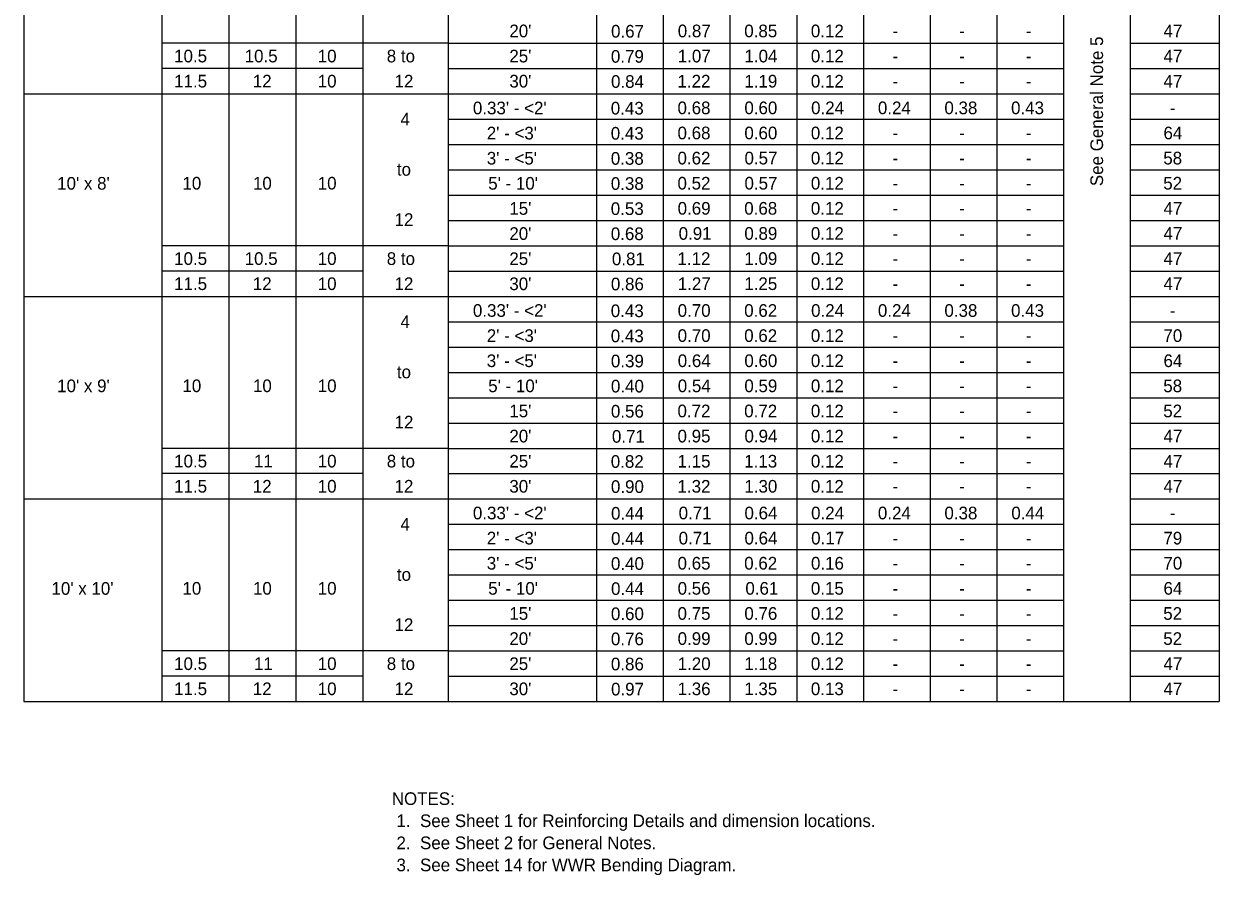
# Model space of a CAD drawing. Extents: x 10346.98 to 10349.19, y 76399.48 to 76400.59.
# Drawn here: x 10347.625 to 10348.22, y 76399.738 to 76400.162 of the extents above; entities that cross this region are included whole.
import ezdxf

# ---------------------------------------------------------------- set-up
doc = ezdxf.new("R2010")
doc.units = 0
doc.layers.add('AdhocPoint_dp', color=7, linetype='Continuous')
doc.layers.add('PlotBorder_dp', color=7, linetype='Continuous')

msp = doc.modelspace()

# ---------------------------------------------------------------- linework, layer by layer
at = {"layer": 'PlotBorder_dp'}
for p, q in [((10347.62504, 76400.49971), (10347.62504, 76399.82469)), ((10348.21977, 76400.49971), (10348.21977, 76399.82469)), ((10347.69367, 76400.47984), (10347.69367, 76399.82469)), ((10347.83612, 76400.47984), (10347.83612, 76399.82469)), ((10347.91, 76400.47984), (10347.91, 76399.82469)), ((10348.17559, 76400.47984), (10348.17559, 76399.82469)), ((10347.72703, 76400.46724), (10347.72703, 76399.82469)), ((10347.76039, 76400.46724), (10347.76039, 76399.82469)), ((10347.79375, 76400.46724), (10347.79375, 76399.82469)), ((10347.9432, 76400.44209), (10347.9432, 76399.82469)), ((10347.97639, 76400.44209), (10347.97639, 76399.82469)), ((10348.00959, 76400.44209), (10348.00959, 76399.82469)), ((10348.04279, 76400.44209), (10348.04279, 76399.82469)), ((10348.07599, 76400.44209), (10348.07599, 76399.82469)), ((10348.07599, 76400.44209), (10348.07599, 76399.82469)), ((10348.10919, 76400.44209), (10348.10919, 76399.82469)), ((10348.14239, 76400.44209), (10348.14239, 76399.82469)), ((10347.83612, 76400.15229), (10347.69367, 76400.15229)), ((10347.83612, 76400.15229), (10348.14239, 76400.15229)), ((10348.17559, 76400.15229), (10348.21977, 76400.15229)), ((10347.79375, 76400.13969), (10347.69367, 76400.13969)), ((10347.83612, 76400.13969), (10348.14239, 76400.13969)), ((10348.17559, 76400.13969), (10348.21977, 76400.13969)), ((10347.62504, 76400.12709), (10348.14239, 76400.12709)), ((10347.83673, 76400.12709), (10347.9089, 76400.12709)), ((10348.17559, 76400.12709), (10348.21977, 76400.12709)), ((10347.83612, 76400.11449), (10348.14239, 76400.11449)), ((10348.17559, 76400.11449), (10348.21977, 76400.11449)), ((10347.83612, 76400.10189), (10348.14239, 76400.10189)), ((10348.17559, 76400.10189), (10348.21977, 76400.10189)), ((10347.83612, 76400.08929), (10348.14239, 76400.08929)), ((10348.17559, 76400.08929), (10348.21977, 76400.08929)), ((10347.83612, 76400.07669), (10348.14239, 76400.07669)), ((10348.17559, 76400.07669), (10348.21977, 76400.07669)), ((10347.83612, 76400.06409), (10348.14239, 76400.06409)), ((10348.17559, 76400.06409), (10348.21977, 76400.06409)), ((10347.83612, 76400.05149), (10347.69367, 76400.05149)), ((10347.83612, 76400.05149), (10348.14239, 76400.05149)), ((10348.17559, 76400.05149), (10348.21977, 76400.05149)), ((10347.79375, 76400.03889), (10347.69367, 76400.03889)), ((10347.83612, 76400.03889), (10348.14239, 76400.03889)), ((10348.17559, 76400.03889), (10348.21977, 76400.03889)), ((10347.62504, 76400.02629), (10348.14239, 76400.02629)), ((10347.83673, 76400.02629), (10347.9089, 76400.02629)), ((10348.17559, 76400.02629), (10348.21977, 76400.02629)), ((10347.83612, 76400.01369), (10348.14239, 76400.01369)), ((10348.17559, 76400.01369), (10348.21977, 76400.01369)), ((10347.83612, 76400.00109), (10348.14239, 76400.00109)), ((10348.17559, 76400.00109), (10348.21977, 76400.00109)), ((10347.83612, 76399.98849), (10348.14239, 76399.98849)), ((10348.17559, 76399.98849), (10348.21977, 76399.98849)), ((10347.83612, 76399.97589), (10348.14239, 76399.97589)), ((10348.17559, 76399.97589), (10348.21977, 76399.97589)), ((10347.83612, 76399.96329), (10348.14239, 76399.96329)), ((10348.17559, 76399.96329), (10348.21977, 76399.96329)), ((10347.83612, 76399.95069), (10347.69367, 76399.95069)), ((10347.83612, 76399.95069), (10348.14239, 76399.95069)), ((10348.17559, 76399.95069), (10348.21977, 76399.95069)), ((10347.79375, 76399.93809), (10347.69367, 76399.93809)), ((10347.83612, 76399.93809), (10348.14239, 76399.93809)), ((10348.17559, 76399.93809), (10348.21977, 76399.93809)), ((10347.62504, 76399.92549), (10348.14239, 76399.92549)), ((10347.83673, 76399.92549), (10347.9089, 76399.92549)), ((10347.83673, 76399.92549), (10347.9089, 76399.92549)), ((10347.83673, 76399.92549), (10347.9089, 76399.92549)), ((10348.17559, 76399.92549), (10348.21977, 76399.92549)), ((10347.83612, 76399.91289), (10348.14239, 76399.91289)), ((10348.17559, 76399.91289), (10348.21977, 76399.91289)), ((10347.83612, 76399.90029), (10348.14239, 76399.90029)), ((10348.17559, 76399.90029), (10348.21977, 76399.90029)), ((10347.83612, 76399.88769), (10348.14239, 76399.88769)), ((10348.17559, 76399.88769), (10348.21977, 76399.88769)), ((10347.83612, 76399.87509), (10348.14239, 76399.87509)), ((10348.17559, 76399.87509), (10348.21977, 76399.87509)), ((10347.83612, 76399.86249), (10348.14239, 76399.86249)), ((10348.17559, 76399.86249), (10348.21977, 76399.86249)), ((10347.83612, 76399.84989), (10347.69367, 76399.84989)), ((10347.83612, 76399.84989), (10348.14239, 76399.84989)), ((10348.17559, 76399.84989), (10348.21977, 76399.84989)), ((10347.79375, 76399.83729), (10347.69367, 76399.83729)), ((10347.83612, 76399.83729), (10348.14239, 76399.83729)), ((10348.17559, 76399.83729), (10348.21977, 76399.83729)), ((10347.62504, 76399.82469), (10348.21977, 76399.82469)), ((10347.83673, 76399.82469), (10347.9089, 76399.82469)), ((10347.83673, 76399.82469), (10347.9089, 76399.82469)), ((10347.83673, 76399.82469), (10347.9089, 76399.82469)), ((10347.83673, 76399.82469), (10347.9089, 76399.82469))]:
    msp.add_line(p, q, dxfattribs=at)

# ---------------------------------------------------------------- texts
at = {"layer": 'AdhocPoint_dp'}
msp.add_text('See General Note 5', height=0.0063, rotation=90, dxfattribs=at).set_placement((10348.16203, 76400.08117))
at = {"layer": 'PlotBorder_dp'}
for s, p in [("20'", (10347.8666, 76400.15526)), ('0.67', (10347.91721, 76400.1551)), ('0.87', (10347.95041, 76400.15526)), ('0.85', (10347.9835, 76400.15526)), ('0.12', (10348.01663, 76400.15526)), ('-', (10348.05726, 76400.15526)), ('-', (10348.09047, 76400.15526)), ('-', (10348.12366, 76400.15526)), ('47', (10348.19212, 76400.15526)), ('10.5', (10347.6998, 76400.14277)), ('10.5', (10347.73489, 76400.14277)), ('10', (10347.77125, 76400.14277)), ('8 to', (10347.8056, 76400.14277)), ("25'", (10347.8666, 76400.14276)), ('0.79', (10347.91714, 76400.1426)), ('1.07', (10347.95041, 76400.14276)), ('1.04', (10347.9836, 76400.14276)), ('0.12', (10348.01663, 76400.14276)), ('-', (10348.05726, 76400.14276)), ('-', (10348.09047, 76400.14276)), ('-', (10348.12366, 76400.14276)), ('47', (10348.19212, 76400.14276)), ('11.5', (10347.6998, 76400.13027)), ('12', (10347.73894, 76400.13027)), ('10', (10347.77125, 76400.13027)), ('12', (10347.80947, 76400.13027)), ("30'", (10347.8666, 76400.13026)), ('0.84', (10347.9172, 76400.1301)), ('1.22', (10347.95027, 76400.13026)), ('1.19', (10347.98354, 76400.13026)), ('0.12', (10348.01663, 76400.13026)), ('-', (10348.05726, 76400.13026)), ('-', (10348.09047, 76400.13026)), ('-', (10348.12366, 76400.13026)), ('47', (10348.19212, 76400.13026)), ("0.33' - <2'", (10347.84847, 76400.11692)), ('0.43', (10347.91707, 76400.11682)), ('0.68', (10347.95029, 76400.11698)), ('0.60', (10347.98355, 76400.11698)), ('0.24', (10348.01675, 76400.11698)), ('0.24', (10348.04999, 76400.11698)), ('0.38', (10348.08309, 76400.11698)), ('0.43', (10348.11625, 76400.11698)), ('4', (10347.81242, 76400.11137)), ('-', (10348.19531, 76400.11698)), ("2' - <3'", (10347.85537, 76400.10442)), ('0.43', (10347.91707, 76400.10432)), ('0.68', (10347.95029, 76400.10448)), ('0.60', (10347.98355, 76400.10448)), ('0.12', (10348.01663, 76400.10448)), ('64', (10348.1921, 76400.10448)), ('-', (10348.05726, 76400.10448)), ('-', (10348.09047, 76400.10448)), ('-', (10348.12366, 76400.10448)), ("3' - <5'", (10347.85537, 76400.09192)), ('0.38', (10347.91709, 76400.09182)), ('0.62', (10347.95027, 76400.09198)), ('0.57', (10347.98361, 76400.09198)), ('0.12', (10348.01663, 76400.09198)), ('58', (10348.192, 76400.09198)), ('to', (10347.81064, 76400.08637)), ('-', (10348.05726, 76400.09198)), ('-', (10348.09047, 76400.09198)), ('-', (10348.12366, 76400.09198)), ("10' x 8'", (10347.64159, 76400.07942)), ('10', (10347.70392, 76400.07947)), ('10', (10347.73901, 76400.07947)), ('10', (10347.77125, 76400.07947)), ("5' - 10'", (10347.85608, 76400.07942)), ('0.38', (10347.91709, 76400.07932)), ('0.52', (10347.95027, 76400.07948)), ('0.57', (10347.98361, 76400.07948)), ('0.12', (10348.01663, 76400.07948)), ('52', (10348.19198, 76400.07948)), ('-', (10348.05726, 76400.07948)), ('-', (10348.09047, 76400.07948)), ('-', (10348.12366, 76400.07948)), ("15'", (10347.8666, 76400.06692)), ('0.53', (10347.91707, 76400.06682)), ('0.69', (10347.95034, 76400.06698)), ('0.68', (10347.98349, 76400.06698)), ('0.12', (10348.01663, 76400.06698)), ('47', (10348.19212, 76400.06698)), ('12', (10347.80947, 76400.06137)), ('-', (10348.05726, 76400.06698)), ('-', (10348.09047, 76400.06698)), ('-', (10348.12366, 76400.06698)), ("20'", (10347.8666, 76400.05442)), ('0.68', (10347.91709, 76400.05432)), ('0.91', (10347.95084, 76400.05448)), ('0.89', (10347.98354, 76400.05448)), ('0.12', (10348.01663, 76400.05448)), ('47', (10348.19212, 76400.05448)), ('-', (10348.05726, 76400.05448)), ('-', (10348.09047, 76400.05448)), ('-', (10348.12366, 76400.05448)), ('10.5', (10347.6998, 76400.04197)), ('10.5', (10347.73489, 76400.04197)), ('10', (10347.77125, 76400.04197)), ('8 to', (10347.8056, 76400.04197)), ("25'", (10347.8666, 76400.04192)), ('0.81', (10347.91764, 76400.04182)), ('1.12', (10347.95027, 76400.04198)), ('1.09', (10347.98354, 76400.04198)), ('0.12', (10348.01663, 76400.04198)), ('-', (10348.05726, 76400.04198)), ('-', (10348.09047, 76400.04198)), ('-', (10348.12366, 76400.04198)), ('47', (10348.19212, 76400.04198)), ('11.5', (10347.6998, 76400.02947)), ('12', (10347.73894, 76400.02947)), ('10', (10347.77125, 76400.02947)), ('12', (10347.80947, 76400.02947)), ("30'", (10347.8666, 76400.02942)), ('0.86', (10347.91714, 76400.02932)), ('1.27', (10347.95041, 76400.02948)), ('1.25', (10347.9835, 76400.02948)), ('0.12', (10348.01663, 76400.02948)), ('-', (10348.05726, 76400.02948)), ('-', (10348.09047, 76400.02948)), ('-', (10348.12366, 76400.02948)), ('47', (10348.19212, 76400.02948)), ("0.33' - <2'", (10347.84847, 76400.01614)), ('0.43', (10347.91707, 76400.01599)), ('0.70', (10347.95035, 76400.01614)), ('0.62', (10347.98347, 76400.01614)), ('0.24', (10348.01675, 76400.01614)), ('0.24', (10348.04999, 76400.01614)), ('0.38', (10348.08309, 76400.01614)), ('0.43', (10348.11625, 76400.01614)), ('4', (10347.81242, 76400.01057)), ('-', (10348.19531, 76400.01614)), ("2' - <3'", (10347.85537, 76400.00364)), ('0.43', (10347.91707, 76400.00349)), ('0.70', (10347.95035, 76400.00364)), ('0.62', (10347.98347, 76400.00364)), ('0.12', (10348.01663, 76400.00364)), ('70', (10348.19206, 76400.00364)), ('-', (10348.05726, 76400.00364)), ('-', (10348.09047, 76400.00364)), ('-', (10348.12366, 76400.00364)), ("3' - <5'", (10347.85537, 76399.99114)), ('0.39', (10347.91714, 76399.99099)), ('0.64', (10347.9504, 76399.99114)), ('0.60', (10347.98355, 76399.99114)), ('0.12', (10348.01663, 76399.99114)), ('64', (10348.1921, 76399.99114)), ('to', (10347.81064, 76399.98557)), ('-', (10348.05726, 76399.99114)), ('-', (10348.09047, 76399.99114)), ('-', (10348.12366, 76399.99114)), ("10' x 9'", (10347.64159, 76399.97864)), ('10', (10347.70392, 76399.97867)), ('10', (10347.73901, 76399.97867)), ('10', (10347.77125, 76399.97867)), ("5' - 10'", (10347.85608, 76399.97864)), ('0.40', (10347.91715, 76399.97849)), ('0.54', (10347.9504, 76399.97864)), ('0.59', (10347.98354, 76399.97864)), ('0.12', (10348.01663, 76399.97864)), ('58', (10348.192, 76399.97864)), ('-', (10348.05726, 76399.97864)), ('-', (10348.09047, 76399.97864)), ('-', (10348.12366, 76399.97864)), ("15'", (10347.8666, 76399.96614)), ('0.56', (10347.91714, 76399.96599)), ('0.72', (10347.95027, 76399.96614)), ('0.72', (10347.98347, 76399.96614)), ('0.12', (10348.01663, 76399.96614)), ('52', (10348.19198, 76399.96614)), ('12', (10347.80947, 76399.96057)), ('-', (10348.05726, 76399.96614)), ('-', (10348.09047, 76399.96614)), ('-', (10348.12366, 76399.96614)), ("20'", (10347.8666, 76399.95364)), ('0.71', (10347.91764, 76399.95349)), ('0.95', (10347.9503, 76399.95364)), ('0.94', (10347.9836, 76399.95364)), ('0.12', (10348.01663, 76399.95364)), ('47', (10348.19212, 76399.95364)), ('-', (10348.05726, 76399.95364)), ('-', (10348.09047, 76399.95364)), ('-', (10348.12366, 76399.95364)), ('10.5', (10347.6998, 76399.94117)), ('11', (10347.7395, 76399.94117)), ('10', (10347.77125, 76399.94117)), ('8 to', (10347.8056, 76399.94117)), ("25'", (10347.8666, 76399.94114)), ('0.82', (10347.91707, 76399.94099)), ('1.15', (10347.9503, 76399.94114)), ('1.13', (10347.98347, 76399.94114)), ('0.12', (10348.01663, 76399.94114)), ('-', (10348.05726, 76399.94114)), ('-', (10348.09047, 76399.94114)), ('-', (10348.12366, 76399.94114)), ('47', (10348.19212, 76399.94114)), ('11.5', (10347.6998, 76399.92867)), ('12', (10347.73894, 76399.92867)), ('10', (10347.77125, 76399.92867)), ('12', (10347.80947, 76399.92867)), ("30'", (10347.8666, 76399.92864)), ('0.90', (10347.91715, 76399.92849)), ('1.32', (10347.95027, 76399.92864)), ('1.30', (10347.98355, 76399.92864)), ('0.12', (10348.01663, 76399.92864)), ('-', (10348.05726, 76399.92864)), ('-', (10348.09047, 76399.92864)), ('-', (10348.12366, 76399.92864)), ('47', (10348.19212, 76399.92864)), ("0.33' - <2'", (10347.84847, 76399.91536)), ('0.44', (10347.9172, 76399.91521)), ('0.71', (10347.95084, 76399.91536)), ('0.64', (10347.9836, 76399.91536)), ('0.24', (10348.01675, 76399.91536)), ('0.24', (10348.04999, 76399.91536)), ('0.38', (10348.08309, 76399.91536)), ('0.44', (10348.11638, 76399.91536)), ('-', (10348.19531, 76399.91536)), ('4', (10347.81242, 76399.90977)), ("2' - <3'", (10347.85537, 76399.90286)), ('0.44', (10347.9172, 76399.90271)), ('0.71', (10347.95084, 76399.90286)), ('0.64', (10347.9836, 76399.90286)), ('0.17', (10348.01677, 76399.90286)), ('79', (10348.19205, 76399.90286)), ('-', (10348.05726, 76399.90286)), ('-', (10348.09047, 76399.90286)), ('-', (10348.12366, 76399.90286)), ("3' - <5'", (10347.85537, 76399.89036)), ('0.40', (10347.91715, 76399.89021)), ('0.65', (10347.9503, 76399.89036)), ('0.62', (10347.98347, 76399.89036)), ('0.16', (10348.01669, 76399.89036)), ('70', (10348.19206, 76399.89036)), ('to', (10347.81064, 76399.88477)), ('-', (10348.05726, 76399.89036)), ('-', (10348.09047, 76399.89036)), ('-', (10348.12366, 76399.89036)), ("10' x 10'", (10347.63876, 76399.87781)), ('10', (10347.70392, 76399.87787)), ('10', (10347.73901, 76399.87787)), ('10', (10347.77125, 76399.87787)), ("5' - 10'", (10347.85608, 76399.87786)), ('0.44', (10347.9172, 76399.87771)), ('0.56', (10347.95034, 76399.87786)), ('0.61', (10347.98404, 76399.87786)), ('0.15', (10348.01665, 76399.87786)), ('64', (10348.1921, 76399.87786)), ('-', (10348.05726, 76399.87786)), ('-', (10348.09047, 76399.87786)), ('-', (10348.12366, 76399.87786)), ("15'", (10347.8666, 76399.86536)), ('0.60', (10347.91715, 76399.86521)), ('0.75', (10347.9503, 76399.86536)), ('0.76', (10347.98354, 76399.86536)), ('0.12', (10348.01663, 76399.86536)), ('52', (10348.19198, 76399.86536)), ('12', (10347.80947, 76399.85977)), ('-', (10348.05726, 76399.86536)), ('-', (10348.09047, 76399.86536)), ('-', (10348.12366, 76399.86536)), ("20'", (10347.8666, 76399.85286)), ('0.76', (10347.91714, 76399.85271)), ('0.99', (10347.95034, 76399.85286)), ('0.99', (10347.98354, 76399.85286)), ('0.12', (10348.01663, 76399.85286)), ('52', (10348.19198, 76399.85286)), ('-', (10348.05726, 76399.85286)), ('-', (10348.09047, 76399.85286)), ('-', (10348.12366, 76399.85286)), ('10.5', (10347.6998, 76399.84037)), ('11', (10347.7395, 76399.84037)), ('10', (10347.77125, 76399.84037)), ('8 to', (10347.8056, 76399.84037)), ("25'", (10347.8666, 76399.84036)), ('1.20', (10347.95035, 76399.84036)), ('1.18', (10347.98349, 76399.84036)), ('0.12', (10348.01663, 76399.84036)), ('47', (10348.19212, 76399.84036)), ('0.86', (10347.91714, 76399.84021)), ('-', (10348.05726, 76399.84036)), ('-', (10348.09047, 76399.84036)), ('-', (10348.12366, 76399.84036)), ('11.5', (10347.6998, 76399.82787)), ('12', (10347.73894, 76399.82787)), ('10', (10347.77125, 76399.82787)), ('12', (10347.80947, 76399.82787)), ("30'", (10347.8666, 76399.82786)), ('0.97', (10347.91721, 76399.82771)), ('1.36', (10347.95034, 76399.82786)), ('1.35', (10347.9835, 76399.82786)), ('0.13', (10348.01662, 76399.82786)), ('-', (10348.05726, 76399.82786)), ('-', (10348.09047, 76399.82786)), ('-', (10348.12366, 76399.82786)), ('47', (10348.19212, 76399.82786)), ('NOTES: ', (10347.8081, 76399.77321)), (' 1.  See Sheet 1 for Reinforcing Details and dimension locations.', (10347.8081, 76399.76221)), (' 2.  See Sheet 2 for General Notes.', (10347.8081, 76399.75121)), (' 3.  See Sheet 14 for WWR Bending Diagram.', (10347.8081, 76399.74021))]:
    msp.add_text(s, height=0.0063, dxfattribs=at).set_placement(p)

doc.saveas('drawing.dxf')
